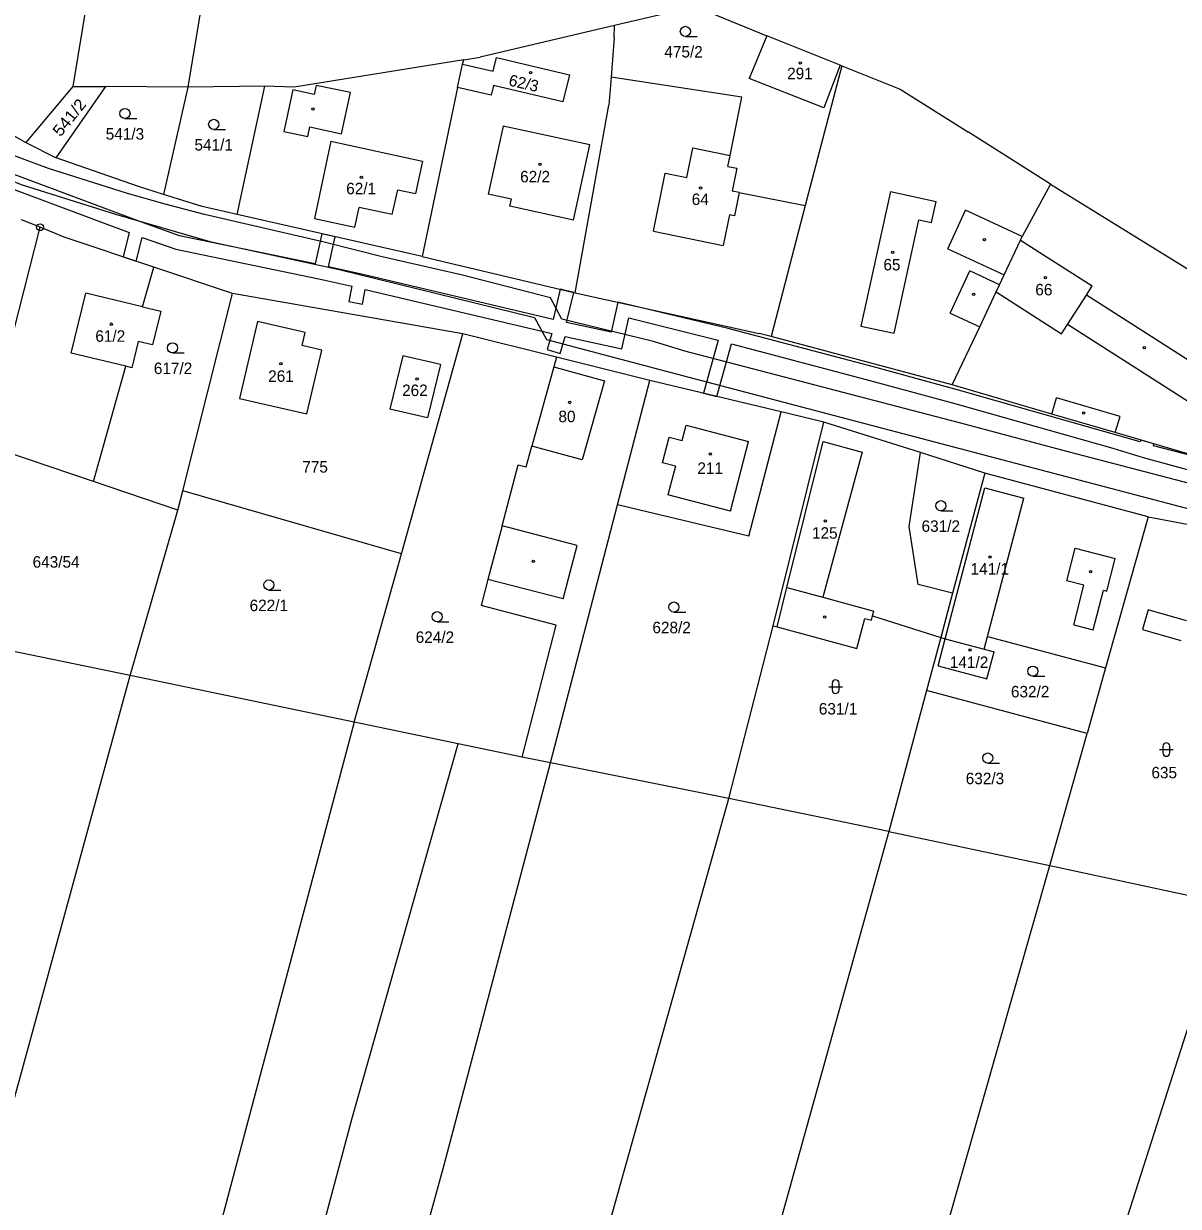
# Model space of a CAD drawing. Extents: x -701211 to -698780, y -1014269 to -1012378.
# Drawn here: x -700178.4 to -700007.4, y -1013587.7 to -1013412.7 of the extents above; entities that cross this region are included whole.
import ezdxf
from ezdxf.enums import TextEntityAlignment as Align

# ---------------------------------------------------------------- set-up
doc = ezdxf.new("R2010")
doc.units = 0
doc.header["$LTSCALE"] = 0.68
for name, color, linetype, lineweight in [('1', 7, 'Continuous', 25), ('13', 7, 'Continuous', 13), ('3', 7, 'Continuous', 25), ('4', 7, 'Continuous', 13), ('5', 7, 'Continuous', 25), ('8', 7, 'Continuous', 25)]:
    doc.layers.add(name, color=color, linetype=linetype, lineweight=lineweight)
doc.layers.add('2', color=7, linetype='Continuous')

msp = doc.modelspace()

# ---------------------------------------------------------------- linework, layer by layer
at = {"layer": '1'}
for p, q in [((-700225.65, -1013403.67), (-700178.09, -1013430.24)), ((-700168.91, -1013408.58), (-700171.13, -1013421.98)), ((-700082.81, -1013408.53), (-700068.37, -1013414.46)), ((-700082.89, -1013411.07), (-700090.93, -1013412.96)), ((-700152.3, -1013411.38), (-700154.07, -1013422.05)), ((-700090.93, -1013412.96), (-700110.79, -1013417.62)), ((-700090.96, -1013414.73), (-700090.93, -1013412.96)), ((-700068.37, -1013414.46), (-700070.97, -1013420.8)), ((-700057.53, -1013418.79), (-700068.37, -1013414.46)), ((-700090.96, -1013414.73), (-700091.42, -1013420.57)), ((-700113.21, -1013418.03), (-700138.32, -1013422.08)), ((-700113.41, -1013418.66), (-700113.21, -1013418.03)), ((-700113.21, -1013418.03), (-700110.79, -1013417.62)), ((-700108.86, -1013419.72), (-700108.38, -1013417.7)), ((-700108.38, -1013417.7), (-700097.57, -1013420.22)), ((-700114.15, -1013422.1), (-700113.41, -1013418.66)), ((-700113.41, -1013418.66), (-700108.86, -1013419.72)), ((-700057.28, -1013418.91), (-700062.67, -1013439.59)), ((-700057.53, -1013418.79), (-700059.93, -1013425.11)), ((-700057.53, -1013418.79), (-700057.28, -1013418.91)), ((-700057.28, -1013418.91), (-700048.62, -1013422.34)), ((-700097.57, -1013420.22), (-700098.57, -1013424.24)), ((-700091.42, -1013420.57), (-700091.74, -1013424.71)), ((-700072.06, -1013423.54), (-700091.42, -1013420.57)), ((-700059.93, -1013425.11), (-700070.97, -1013420.8)), ((-700171.13, -1013421.98), (-700178.09, -1013430.24)), ((-700171.13, -1013421.98), (-700166.23, -1013421.97)), ((-700154.07, -1013422.05), (-700166.23, -1013421.97)), ((-700154.07, -1013422.05), (-700157.7, -1013437.93)), ((-700142.67, -1013421.92), (-700154.07, -1013422.05)), ((-700146.79, -1013440.89), (-700142.67, -1013421.92)), ((-700138.32, -1013422.08), (-700142.67, -1013421.92)), ((-700114.15, -1013422.1), (-700119.39, -1013447.14)), ((-700109.16, -1013423.27), (-700114.15, -1013422.1)), ((-700108.82, -1013421.83), (-700109.16, -1013423.27)), ((-700098.57, -1013424.24), (-700108.82, -1013421.83)), ((-700048.62, -1013422.34), (-700038.52, -1013428.73)), ((-700096.76, -1013452.5), (-700091.74, -1013424.71)), ((-700073.81, -1013432.18), (-700072.06, -1013423.54)), ((-700026.39, -1013436.44), (-700038.52, -1013428.73)), ((-700161.38, -1013436.77), (-700173.6, -1013432.53)), ((-700074.14, -1013433.8), (-700073.81, -1013432.18)), ((-700157.7, -1013437.93), (-700161.38, -1013436.77)), ((-700026.39, -1013436.44), (-700030.55, -1013444.15)), ((-700026.39, -1013436.44), (-699996.22, -1013455.06)), ((-700151.98, -1013439.72), (-700157.7, -1013437.93)), ((-700072.44, -1013437.66), (-700073.5, -1013437.45)), ((-700072.44, -1013437.66), (-700062.67, -1013439.59)), ((-700146.79, -1013440.89), (-700151.98, -1013439.72)), ((-700119.39, -1013447.14), (-700146.79, -1013440.89)), ((-700062.67, -1013439.59), (-700067.72, -1013458.97)), ((-700175.97, -1013442.8), (-700178.7, -1013441.69)), ((-700183.58, -1013472.72), (-700175.97, -1013442.8)), ((-700172.41, -1013444.25), (-700175.97, -1013442.8)), ((-700159.14, -1013448.69), (-700172.41, -1013444.25)), ((-700030.8, -1013444.69), (-700030.55, -1013444.15)), ((-700033.24, -1013449.86), (-700030.8, -1013444.69)), ((-700119.39, -1013447.14), (-700096.76, -1013452.5)), ((-700160.79, -1013454.56), (-700159.14, -1013448.69)), ((-700147.47, -1013452.59), (-700159.14, -1013448.69)), ((-700034.42, -1013452.37), (-700033.91, -1013451.3)), ((-700033.91, -1013451.3), (-700033.24, -1013449.86)), ((-700154.85, -1013481.82), (-700147.47, -1013452.59)), ((-700096.76, -1013452.5), (-700069.48, -1013458.5)), ((-700036.84, -1013457.52), (-700034.42, -1013452.37)), ((-700160.79, -1013454.56), (-700158.1, -1013455.21)), ((-700158.1, -1013455.21), (-700159.31, -1013460.22)), ((-700143.78, -1013456.72), (-700146.46, -1013468.13)), ((-700136.72, -1013458.38), (-700143.78, -1013456.72)), ((-700137.17, -1013460.31), (-700136.72, -1013458.38)), ((-700040.91, -1013466.14), (-700036.84, -1013457.52)), ((-700161.44, -1013459.7), (-700162.38, -1013463.59)), ((-700159.31, -1013460.22), (-700161.44, -1013459.7)), ((-700099.51, -1013462.04), (-700113.35, -1013458.59)), ((-700067.72, -1013458.97), (-700069.48, -1013458.5)), ((-700040.91, -1013466.14), (-700067.72, -1013458.97)), ((-700134.25, -1013460.99), (-700137.17, -1013460.31)), ((-700136.47, -1013470.42), (-700134.25, -1013460.99)), ((-700122.26, -1013461.81), (-700124.19, -1013469.71)), ((-700116.69, -1013463.12), (-700122.26, -1013461.81)), ((-700168.07, -1013480.42), (-700163.27, -1013463.37)), ((-700162.38, -1013463.59), (-700163.27, -1013463.37)), ((-700116.69, -1013463.12), (-700118.62, -1013471.02)), ((-700099.9, -1013463.45), (-700103.17, -1013475.18)), ((-700099.51, -1013462.04), (-700099.9, -1013463.45)), ((-700085.7, -1013465.48), (-700099.51, -1013462.04)), ((-700090.48, -1013483.87), (-700085.7, -1013465.48)), ((-700066.25, -1013470.12), (-700085.7, -1013465.48)), ((-700026.19, -1013470.44), (-700040.91, -1013466.14)), ((-700146.46, -1013468.13), (-700136.47, -1013470.42)), ((-700118.62, -1013471.02), (-700124.19, -1013469.71)), ((-700071.02, -1013488.51), (-700066.25, -1013470.12)), ((-700059.92, -1013471.63), (-700066.25, -1013470.12)), ((-700016.78, -1013473.19), (-700026.19, -1013470.44)), ((-700067.42, -1013501.76), (-700059.92, -1013471.63)), ((-700045.61, -1013476.15), (-700059.92, -1013471.63)), ((-700002.55, -1013477.36), (-700016.78, -1013473.19)), ((-700104.02, -1013478.27), (-700103.17, -1013475.18)), ((-700168.07, -1013480.42), (-700180.88, -1013476.1)), ((-700047.3, -1013487.08), (-700045.61, -1013476.15)), ((-700036.08, -1013479.17), (-700045.61, -1013476.15)), ((-700107.57, -1013486.99), (-700105.17, -1013477.95)), ((-700105.17, -1013477.95), (-700104.02, -1013478.27)), ((-700036.08, -1013479.17), (-700040.86, -1013496.95)), ((-700011.93, -1013485.64), (-700036.08, -1013479.17)), ((-700155.56, -1013484.64), (-700168.07, -1013480.42)), ((-700155.56, -1013484.64), (-700154.85, -1013481.82)), ((-700122.47, -1013491.1), (-700154.85, -1013481.82)), ((-700162.62, -1013509.15), (-700155.56, -1013484.64)), ((-700100.4, -1013522.07), (-700090.48, -1013483.87)), ((-700071.02, -1013488.51), (-700090.48, -1013483.87)), ((-700011.93, -1013485.64), (-700018.21, -1013507.98)), ((-700011.93, -1013485.64), (-699995.35, -1013488.75)), ((-700107.57, -1013486.99), (-700109.65, -1013494.92)), ((-700045.96, -1013495.65), (-700047.3, -1013487.08)), ((-700129.45, -1013516.02), (-700122.47, -1013491.1)), ((-700109.65, -1013494.92), (-700110.67, -1013498.79)), ((-700040.86, -1013496.95), (-700045.96, -1013495.65)), ((-700040.86, -1013496.95), (-700042.62, -1013503.52)), ((-700099.54, -1013501.67), (-700110.67, -1013498.79)), ((-700052.87, -1013500.93), (-700052.7, -1013500.3)), ((-700052.7, -1013500.3), (-700042.62, -1013503.52)), ((-700011.9, -1013499.4), (-700012.73, -1013502.3)), ((-700006.25, -1013501.02), (-700011.9, -1013499.4)), ((-700104.59, -1013521.2), (-700099.54, -1013501.67)), ((-700074.01, -1013527.35), (-700067.42, -1013501.76)), ((-700067.42, -1013501.76), (-700066.83, -1013501.92)), ((-700066.83, -1013501.92), (-700055.04, -1013505.11)), ((-700055.04, -1013505.11), (-700053.84, -1013500.67)), ((-700053.84, -1013500.67), (-700052.87, -1013500.93)), ((-700162.62, -1013509.15), (-700191.33, -1013503.18)), ((-700042.62, -1013503.52), (-700044.71, -1013511.33)), ((-700043.01, -1013507.72), (-700041.95, -1013503.7)), ((-700042.62, -1013503.52), (-700041.95, -1013503.7)), ((-700041.95, -1013503.7), (-700036.21, -1013505.21)), ((-700012.73, -1013502.3), (-700007.08, -1013503.93)), ((-700036.21, -1013505.21), (-700034.71, -1013505.61)), ((-700035.78, -1013509.62), (-700034.71, -1013505.61)), ((-700213.5, -1013694.58), (-700162.62, -1013509.15)), ((-700129.45, -1013516.02), (-700162.62, -1013509.15)), ((-700043.01, -1013507.72), (-700035.78, -1013509.62)), ((-700018.21, -1013507.98), (-700020.94, -1013517.7)), ((-700044.71, -1013511.33), (-700050.31, -1013532.22)), ((-700020.94, -1013517.7), (-700044.71, -1013511.33)), ((-700129.45, -1013516.02), (-700169.53, -1013666.16)), ((-700114.07, -1013519.22), (-700129.45, -1013516.02)), ((-700026.49, -1013537.22), (-700020.94, -1013517.7)), ((-700129.69, -1013574.41), (-700114.07, -1013519.22)), ((-700104.59, -1013521.2), (-700114.07, -1013519.22)), ((-700100.4, -1013522.07), (-700104.59, -1013521.2)), ((-700116.14, -1013581.53), (-700100.4, -1013522.07)), ((-700074.01, -1013527.35), (-700100.4, -1013522.07)), ((-700103.11, -1013630.91), (-700074.01, -1013527.35)), ((-700050.31, -1013532.22), (-700074.01, -1013527.35)), ((-700050.31, -1013532.22), (-700092.33, -1013683.22)), ((-700050.31, -1013532.22), (-700026.49, -1013537.22)), ((-700070.53, -1013691.94), (-700026.49, -1013537.22)), ((-700026.49, -1013537.22), (-700000.2, -1013542.89)), ((-700000.2, -1013542.89), (-700050.45, -1013699.97)), ((-700166.66, -1013711.75), (-700129.69, -1013574.41)), ((-700146.99, -1013693.42), (-700116.14, -1013581.53))]:
    msp.add_line(p, q, dxfattribs=at)
for points in [[(-700178.09, -1013430.24), (-700173.6, -1013432.53), (-700166.23, -1013421.97)], [(-700074.14, -1013433.8), (-700072.81, -1013434.07), (-700073.5, -1013437.45)], [(-700122.47, -1013491.1), (-700113.35, -1013458.59), (-700147.47, -1013452.59)], [(-700036.21, -1013505.21), (-700035.72, -1013503.37), (-700018.21, -1013507.98)]]:
    msp.add_lwpolyline(points, dxfattribs=at)
at = {"layer": '13'}
for points in [[(-700236.22, -1013404.79), (-700218.26, -1013416.44), (-700211.83, -1013420.29), (-700200.74, -1013426.28), (-700183.24, -1013434.69), (-700178.63, -1013436.5), (-700164.79, -1013440.87), (-700150.84, -1013444.89), (-700139.87, -1013447.26), (-700131.68, -1013449.03), (-700102.76, -1013456.15), (-700101.01, -1013459.41), (-700079.92, -1013464.99), (-699992.36, -1013488.02)], [(-700001.06, -1013481.97), (-700024.67, -1013475.8), (-700038.89, -1013471.99), (-700080.49, -1013461.11), (-700085.15, -1013459.71), (-700098.71, -1013456.38), (-700100.41, -1013453.25), (-700113.41, -1013449.89), (-700125.33, -1013447.16), (-700133.92, -1013444.98), (-700151.62, -1013440.92), (-700157.43, -1013439.4), (-700163.03, -1013437.78), (-700174.7, -1013434.09), (-700180.31, -1013432.02), (-700185.79, -1013429.64), (-700196.55, -1013424.33), (-700202.96, -1013421), (-700208.55, -1013417.96), (-700218.95, -1013411.78)], [(-700002.55, -1013477.36), (-700011.13, -1013475.12), (-700011.07, -1013474.86), (-700013.02, -1013474.29), (-700013.09, -1013474.55), (-700039.97, -1013466.91), (-700052.6, -1013463.46), (-700074.07, -1013457.77), (-700090.42, -1013453.9), (-700091.42, -1013458.34), (-700098.02, -1013456.9), (-700096.96, -1013452.45), (-700098.94, -1013451.98), (-700100, -1013456.45), (-700128.36, -1013449.75), (-700133.26, -1013448.63), (-700132.25, -1013444.21), (-700134.23, -1013443.75), (-700135.25, -1013448.2), (-700155.3, -1013444.06), (-700161.2, -1013441.97), (-700182.36, -1013434.06)], [(-700181, -1013436.77), (-700162.76, -1013443.59), (-700163.65, -1013447.18), (-700161.72, -1013447.83), (-700160.84, -1013444.29), (-700155.85, -1013446.05), (-700134.7, -1013450.42), (-700129.79, -1013451.54), (-700130.23, -1013453.76), (-700128.23, -1013454.16), (-700127.81, -1013452), (-700100.21, -1013458.53), (-700100.9, -1013460.89), (-700098.95, -1013461.46), (-700098.22, -1013458.97), (-700089.85, -1013460.8), (-700088.82, -1013456.18), (-700075.59, -1013459.52), (-700077.76, -1013467.37), (-700075.78, -1013467.85), (-700073.62, -1013460.03), (-700053.14, -1013465.45), (-700040.52, -1013468.9), (-700017.12, -1013475.5), (-700012.63, -1013476.85), (-699993.48, -1013482.08)]]:
    msp.add_lwpolyline(points, dxfattribs=at)
at = {"layer": '3'}
for p, q in [((-700080.433, -1013414.56), (-700078.683, -1013414.56)), ((-700163.393, -1013426.71), (-700161.643, -1013426.71)), ((-700150.253, -1013428.32), (-700148.503, -1013428.32)), ((-700156.363, -1013461.4), (-700154.613, -1013461.4)), ((-700042.593, -1013484.75), (-700040.843, -1013484.75)), ((-700142.083, -1013496.48), (-700140.333, -1013496.48)), ((-700082.123, -1013499.75), (-700080.373, -1013499.75)), ((-700117.183, -1013501.18), (-700115.433, -1013501.18)), ((-700059.181, -1013510.781), (-700057.179, -1013510.781)), ((-700058.681, -1013510.281), (-700058.681, -1013511.282)), ((-700057.679, -1013511.282), (-700057.679, -1013510.281)), ((-700028.983, -1013509.24), (-700027.233, -1013509.24)), ((-700009.721, -1013519.581), (-700009.721, -1013520.582)), ((-700008.719, -1013520.582), (-700008.719, -1013519.581)), ((-700010.221, -1013520.081), (-700008.219, -1013520.081)), ((-700035.663, -1013522.09), (-700033.913, -1013522.09))]:
    msp.add_line(p, q, dxfattribs=at)
for centre in [(-700080.4329, -1013413.8098), (-700163.3929, -1013425.9598), (-700150.2529, -1013427.5698), (-700156.3629, -1013460.6498), (-700042.5929, -1013483.9998), (-700142.0829, -1013495.7298), (-700082.1229, -1013498.9998), (-700117.1829, -1013500.4298), (-700028.9829, -1013508.4898), (-700035.6629, -1013521.3398)]:
    msp.add_circle(centre, 0.75, dxfattribs=at)
for centre, start, end in [((-700058.18, -1013510.2809), 0, 180), ((-700058.18, -1013511.2809), 180, 359.98789), ((-700009.22, -1013519.5809), 0, 180), ((-700009.22, -1013520.5809), 180, 359.98789)]:
    msp.add_arc(centre, 0.5, start, end, dxfattribs=at)
at = {"layer": '4'}
for p, q in [((-700138.56, -1013422.46), (-700139.88, -1013428.62)), ((-700135.38, -1013423.14), (-700138.56, -1013422.46)), ((-700135.1, -1013421.8), (-700135.38, -1013423.14)), ((-700130.02, -1013422.86), (-700135.1, -1013421.8)), ((-700131.33, -1013428.96), (-700130.02, -1013422.86)), ((-700139.88, -1013428.62), (-700136.33, -1013429.38)), ((-700136.33, -1013429.38), (-700136.03, -1013427.95)), ((-700136.03, -1013427.95), (-700131.33, -1013428.96)), ((-700107.38, -1013427.82), (-700109.61, -1013437.9)), ((-700094.59, -1013430.58), (-700107.38, -1013427.82)), ((-700132.91, -1013430.04), (-700119.33, -1013433.03)), ((-700097.01, -1013441.76), (-700094.59, -1013430.58)), ((-700080.19, -1013435.44), (-700079.31, -1013431.07)), ((-700079.31, -1013431.07), (-700073.81, -1013432.18)), ((-700119.33, -1013433.03), (-700120.38, -1013437.82)), ((-700085.15, -1013443.4), (-700083.4, -1013434.79)), ((-700083.4, -1013434.79), (-700080.19, -1013435.44)), ((-700123.85, -1013440.89), (-700123.02, -1013437.24)), ((-700123.02, -1013437.24), (-700120.38, -1013437.82)), ((-700106.19, -1013438.66), (-700109.61, -1013437.9)), ((-700106.42, -1013439.68), (-700106.19, -1013438.66)), ((-700072.44, -1013437.66), (-700073.14, -1013441.09)), ((-700050.08, -1013437.5), (-700054.45, -1013457.41)), ((-700050.08, -1013437.5), (-700043.31, -1013438.98)), ((-700043.99, -1013442.1), (-700043.31, -1013438.98)), ((-700129.34, -1013442.8), (-700128.71, -1013439.87)), ((-700123.85, -1013440.89), (-700128.71, -1013439.87)), ((-700097.01, -1013441.76), (-700106.42, -1013439.68)), ((-700041.59, -1013445.99), (-700038.94, -1013440.26)), ((-700030.55, -1013444.15), (-700038.94, -1013440.26)), ((-700073.89, -1013440.94), (-700074.82, -1013445.5)), ((-700073.14, -1013441.09), (-700073.89, -1013440.94)), ((-700049.52, -1013458.49), (-700045.84, -1013441.69)), ((-700045.84, -1013441.69), (-700043.99, -1013442.1)), ((-700085.15, -1013443.4), (-700074.82, -1013445.5)), ((-700041.59, -1013445.99), (-700033.24, -1013449.86)), ((-700030.8, -1013444.69), (-700020.18, -1013451.49)), ((-700041.21, -1013455.5), (-700038.32, -1013449.26)), ((-700033.91, -1013451.3), (-700038.32, -1013449.26)), ((-700171.34, -1013461.43), (-700169.2, -1013452.56)), ((-700160.79, -1013454.56), (-700169.2, -1013452.56)), ((-700034.42, -1013452.37), (-700024.72, -1013458.58)), ((-700023.84, -1013457.2), (-700021.04, -1013452.83)), ((-700041.21, -1013455.5), (-700036.84, -1013457.52)), ((-700054.45, -1013457.41), (-700049.52, -1013458.49)), ((-700024.72, -1013458.58), (-700023.84, -1013457.2)), ((-700004.17, -1013469.79), (-700023.84, -1013457.2)), ((-700163.27, -1013463.37), (-700171.34, -1013461.43)), ((-700099.9, -1013463.45), (-700092.42, -1013465.5)), ((-700092.42, -1013465.5), (-700095.69, -1013477.23)), ((-700026.19, -1013470.44), (-700025.49, -1013468.04)), ((-700016.08, -1013470.79), (-700025.49, -1013468.04)), ((-700080.9, -1013474.37), (-700080.31, -1013472.09)), ((-700080.31, -1013472.09), (-700071.07, -1013474.49)), ((-700016.78, -1013473.19), (-700016.08, -1013470.79)), ((-700095.69, -1013477.23), (-700103.17, -1013475.18)), ((-700073.77, -1013484.8), (-700071.07, -1013474.49)), ((-700065.39, -1013496.11), (-700060.03, -1013474.52)), ((-700060.03, -1013474.52), (-700054.24, -1013476.09)), ((-700081.9, -1013478.14), (-700083.79, -1013477.65)), ((-700054.24, -1013476.09), (-700060.06, -1013497.56)), ((-700081.9, -1013478.14), (-700083.01, -1013482.4)), ((-700073.77, -1013484.8), (-700083.01, -1013482.4)), ((-700041.95, -1013503.7), (-700036.07, -1013481.36)), ((-700036.07, -1013481.36), (-700030.33, -1013482.87)), ((-700035.72, -1013503.37), (-700030.33, -1013482.87)), ((-700096.44, -1013489.87), (-700107.57, -1013486.99)), ((-700098.52, -1013497.8), (-700096.44, -1013489.87)), ((-700023.95, -1013495.11), (-700022.7, -1013490.27)), ((-700022.7, -1013490.27), (-700016.8, -1013491.79)), ((-700018.05, -1013496.63), (-700016.8, -1013491.79)), ((-700098.52, -1013497.8), (-700109.65, -1013494.92)), ((-700066.83, -1013501.92), (-700065.39, -1013496.11)), ((-700065.39, -1013496.11), (-700060.06, -1013497.56)), ((-700018.52, -1013496.51), (-700018.05, -1013496.63)), ((-700060.06, -1013497.56), (-700052.51, -1013499.61)), ((-700052.7, -1013500.3), (-700052.51, -1013499.61))]:
    msp.add_line(p, q, dxfattribs=at)
for points in [[(-700132.91, -1013430.04), (-700135.34, -1013441.51), (-700129.34, -1013442.8)], [(-700001.37, -1013465.42), (-700021.04, -1013452.83), (-700020.18, -1013451.49)], [(-700083.79, -1013477.65), (-700082.81, -1013473.87), (-700080.9, -1013474.37)], [(-700022.94, -1013501.62), (-700021.43, -1013495.76), (-700023.95, -1013495.11)], [(-700022.94, -1013501.62), (-700020.03, -1013502.37), (-700018.52, -1013496.51)]]:
    msp.add_lwpolyline(points, dxfattribs=at)
at = {"layer": '5'}
for centre in [(-700103.3368, -1013419.9292), (-700063.4168, -1013418.4792), (-700135.5568, -1013425.2792), (-700101.9468, -1013433.4992), (-700128.3768, -1013435.3892), (-700078.1868, -1013436.9892), (-700036.1468, -1013444.6292), (-700049.7368, -1013446.5192), (-700027.1268, -1013450.2692), (-700037.7568, -1013452.7092), (-700165.4168, -1013457.1392), (-700012.4868, -1013460.6092), (-700140.3168, -1013462.9792), (-700120.1368, -1013465.2692), (-700097.5568, -1013468.7292), (-700021.4768, -1013470.2892), (-700076.7168, -1013476.3392), (-700059.7168, -1013486.2492), (-700035.3268, -1013491.6092), (-700102.9368, -1013492.2392), (-700020.4268, -1013493.7692), (-700059.7868, -1013500.4792), (-700038.2868, -1013505.3492)]:
    msp.add_circle(centre, 0.175, dxfattribs=at)
at = {"layer": '8'}
for radius in [0.5, 0.0303]:
    msp.add_circle((-700175.97, -1013442.7999), radius, dxfattribs=at)

# ---------------------------------------------------------------- texts
at = {"layer": '2'}
for s, p in [('475/2', (-700083.54, -1013417.685)), ('291', (-700065.36, -1013420.885)), ('62/2', (-700104.89, -1013436.155)), ('62/1', (-700130.64, -1013437.915)), ('64', (-700079.49, -1013439.505)), ('65', (-700051.11, -1013449.185)), ('66', (-700028.62, -1013452.875)), ('61/2', (-700167.78, -1013459.745)), ('617/2', (-700159.12, -1013464.525)), ('261', (-700142.19, -1013465.675)), ('262', (-700122.37, -1013467.775)), ('80', (-700099.22, -1013471.645)), ('775', (-700137.14, -1013479.105)), ('211', (-700078.65, -1013479.295)), ('631/2', (-700045.46, -1013487.875)), ('125', (-700061.68, -1013488.885)), ('141/1', (-700038.2, -1013494.195)), ('622/1', (-700144.94, -1013499.605)), ('628/2', (-700085.31, -1013502.875)), ('624/2', (-700120.35, -1013504.305)), ('141/2', (-700041.27, -1013508.015)), ('632/2', (-700032.23, -1013512.365)), ('631/1', (-700060.67, -1013514.905)), ('635', (-700011.43, -1013524.345)), ('632/3', (-700038.92, -1013525.215))]:
    msp.add_text(s, height=1.7, dxfattribs=at).set_placement(p)
msp.add_text('62/3', height=1.7, rotation=347, dxfattribs=at).set_placement((-700106.695, -1013421.804))
at = {"layer": '2', "width": 1.1}
msp.add_text('541/2', height=1.7, rotation=51, dxfattribs=at).set_placement((-700172.939, -1013429.517))
at = {"layer": '2'}
for s, p in [('541/3', (-700163.4, -1013429.835)), ('541/1', (-700150.26, -1013431.445)), ('643/54', (-700173.59, -1013493.165))]:
    msp.add_text(s, height=1.7, dxfattribs=at).set_placement(p, align=Align.CENTER)

doc.saveas('drawing.dxf')
